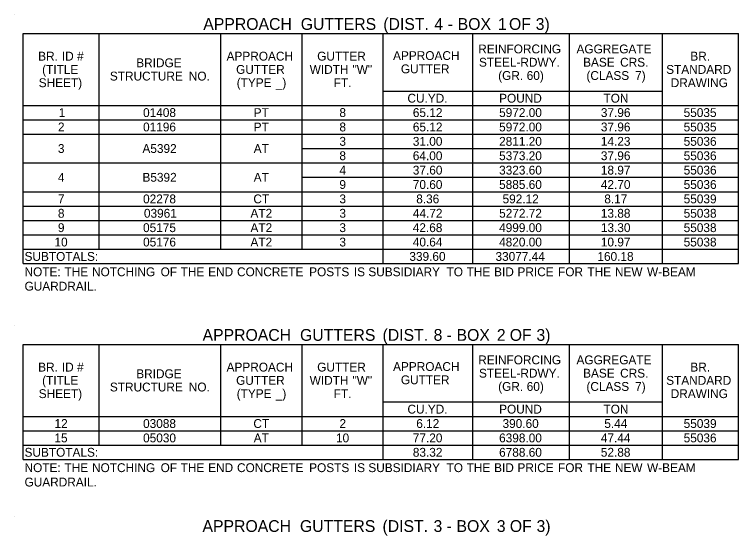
# Model space of a CAD drawing. Extents: x 540541 to 1930787, y -1948574 to 596640.
# Drawn here: x 544342.1 to 544833.1, y -1948134.4 to -1947781.3 of the extents above; entities that cross this region are included whole.
import ezdxf

# ---------------------------------------------------------------- set-up
doc = ezdxf.new("R2010")
doc.units = 0
doc.layers.add('Default', color=7, linetype='Continuous')
doc.layers.add('R_Border', color=7, linetype='Continuous')

msp = doc.modelspace()

# ---------------------------------------------------------------- linework, layer by layer
at = {"layer": 'Default'}
for p, q in [((544347.93, -1947794.12), (544833.09, -1947794.12)), ((544347.93, -1947950.12), (544347.93, -1947794.12)), ((544347.93, -1947950.12), (544347.93, -1947794.12)), ((544399.41, -1947940.37), (544399.41, -1947794.12)), ((544482.09, -1947940.37), (544482.09, -1947794.12)), ((544537.08, -1947940.37), (544537.08, -1947794.12)), ((544592.07, -1947950.12), (544592.07, -1947794.12)), ((544652.91, -1947940.37), (544652.91, -1947794.12)), ((544718.43, -1947940.37), (544718.43, -1947794.12)), ((544781.61, -1947842.87), (544781.61, -1947794.12)), ((544781.61, -1947950.12), (544781.61, -1947794.12)), ((544833.09, -1947950.12), (544833.09, -1947794.12)), ((544592.07, -1947833.12), (544781.61, -1947833.12)), ((544652.91, -1947881.87), (544652.91, -1947833.12)), ((544718.43, -1947881.87), (544718.43, -1947833.12)), ((544347.93, -1947842.87), (544781.61, -1947842.87)), ((544399.41, -1947862.37), (544399.41, -1947842.87)), ((544482.09, -1947852.62), (544482.09, -1947842.87)), ((544781.61, -1947842.87), (544833.09, -1947842.87)), ((544347.93, -1947852.62), (544781.61, -1947852.62)), ((544592.07, -1947852.62), (544718.43, -1947852.62)), ((544718.43, -1947852.62), (544833.09, -1947852.62)), ((544347.93, -1947862.37), (544781.61, -1947862.37)), ((544592.07, -1947862.37), (544718.43, -1947862.37)), ((544718.43, -1947862.37), (544833.09, -1947862.37)), ((544781.61, -1947881.87), (544781.61, -1947862.37)), ((544537.08, -1947872.12), (544781.61, -1947872.12)), ((544592.07, -1947872.12), (544718.43, -1947872.12)), ((544718.43, -1947872.12), (544833.09, -1947872.12)), ((544347.93, -1947881.87), (544833.09, -1947881.87)), ((544592.07, -1947881.87), (544718.43, -1947881.87)), ((544718.43, -1947881.87), (544833.09, -1947881.87)), ((544537.08, -1947891.62), (544718.43, -1947891.62)), ((544537.08, -1947891.62), (544652.91, -1947891.62)), ((544652.91, -1947891.62), (544833.09, -1947891.62)), ((544718.43, -1947901.37), (544718.43, -1947891.62)), ((544781.61, -1947901.37), (544781.61, -1947891.62)), ((544347.93, -1947901.37), (544537.08, -1947901.37)), ((544347.93, -1947901.37), (544482.09, -1947901.37)), ((544399.41, -1947940.37), (544399.41, -1947901.37)), ((544482.09, -1947901.37), (544833.09, -1947901.37)), ((544482.09, -1947911.12), (544482.09, -1947901.37)), ((544718.43, -1947901.37), (544833.09, -1947901.37)), ((544347.93, -1947911.12), (544833.09, -1947911.12)), ((544347.93, -1947920.87), (544833.09, -1947920.87)), ((544482.09, -1947940.37), (544482.09, -1947920.87)), ((544347.93, -1947930.62), (544833.09, -1947930.62)), ((544347.93, -1947940.37), (544833.09, -1947940.37)), ((544592.07, -1947950.12), (544592.07, -1947940.37)), ((544652.91, -1947950.12), (544652.91, -1947940.37)), ((544652.91, -1947950.12), (544652.91, -1947940.37)), ((544718.43, -1947950.12), (544718.43, -1947940.37)), ((544718.43, -1947950.12), (544718.43, -1947940.37)), ((544781.61, -1947950.12), (544781.61, -1947940.37)), ((544347.93, -1947950.12), (544833.09, -1947950.12)), ((544347.93, -1948004.88), (544833.09, -1948004.88)), ((544347.93, -1948082.88), (544347.93, -1948004.88)), ((544347.93, -1948082.88), (544347.93, -1948004.88)), ((544399.41, -1948073.13), (544399.41, -1948004.88)), ((544482.09, -1948073.13), (544482.09, -1948004.88)), ((544537.08, -1948073.13), (544537.08, -1948004.88)), ((544592.07, -1948082.88), (544592.07, -1948004.88)), ((544652.91, -1948082.88), (544652.91, -1948004.88)), ((544718.43, -1948082.88), (544718.43, -1948004.88)), ((544781.61, -1948053.63), (544781.61, -1948004.88)), ((544781.61, -1948082.88), (544781.61, -1948004.88)), ((544833.09, -1948082.88), (544833.09, -1948004.88)), ((544592.07, -1948043.88), (544781.61, -1948043.88)), ((544652.91, -1948053.63), (544652.91, -1948043.88)), ((544718.43, -1948053.63), (544718.43, -1948043.88)), ((544347.93, -1948053.63), (544833.09, -1948053.63)), ((544399.41, -1948063.38), (544399.41, -1948053.63)), ((544482.09, -1948063.38), (544482.09, -1948053.63)), ((544781.61, -1948053.63), (544833.09, -1948053.63)), ((544347.93, -1948063.38), (544718.43, -1948063.38)), ((544347.93, -1948063.38), (544652.91, -1948063.38)), ((544652.91, -1948063.38), (544833.09, -1948063.38)), ((544347.93, -1948073.13), (544833.09, -1948073.13)), ((544592.07, -1948082.88), (544592.07, -1948073.13)), ((544652.91, -1948082.88), (544652.91, -1948073.13)), ((544718.43, -1948082.88), (544718.43, -1948073.13)), ((544781.61, -1948082.88), (544781.61, -1948073.13)), ((544347.93, -1948082.88), (544833.09, -1948082.88))]:
    msp.add_line(p, q, dxfattribs=at)
at = {"layer": 'R_Border'}
for p, q in [((544342.08, -1947781.25), (544342.08, -1947781.25)), ((544342.08, -1947992.01), (544342.08, -1947992.01)), ((544342.08, -1948121.57), (544342.08, -1948121.57))]:
    msp.add_line(p, q, dxfattribs=at)

# ---------------------------------------------------------------- texts
at = {"layer": 'Default'}
for s, height, p in [('APPROACH', 8, (544470.13, -1947791.69)), (' GUTTERS', 8, (544533.25, -1947791.69)), (' (DIST.', 8, (544589.22, -1947791.69)), (' 4', 8, (544623.84, -1947791.69)), (' BOX', 8, (544639.65, -1947791.69)), (' 1', 8, (544666.96, -1947791.69)), (' OF', 8, (544674.47, -1947791.69)), (' 3)', 8, (544692.58, -1947791.69)), (' -', 8, (544632.9, -1947791.69)), ('REINFORCING', 6, (544656.58, -1947807.62)), ('AGGREGATE', 6, (544723.21, -1947807.62)), ('BR.', 6, (544358.15, -1947812.5)), (' ID', 6, (544372.01, -1947812.5)), (' #', 6, (544382.3, -1947812.5)), ('APPROACH', 6, (544485.92, -1947812.5)), ('GUTTER', 6, (544547.36, -1947812.5)), ('APPROACH', 6, (544598.82, -1947812.12)), ('BR.', 6, (544800.42, -1947812.5)), ('BRIDGE', 6, (544424.66, -1947817)), ('STEEL-RDWY.', 6, (544657.08, -1947816.62)), ('BASE', 6, (544727.69, -1947816.62)), (' CRS.', 6, (544750.57, -1947816.62)), ('(TITLE', 6, (544360.84, -1947821.5)), ('GUTTER', 6, (544492.37, -1947821.5)), ('WIDTH', 6, (544542.28, -1947821.5)), (' "W"', 6, (544569.1, -1947821.5)), ('GUTTER', 6, (544604.11, -1947821.12)), ('STANDARD', 6, (544784.04, -1947821.5)), ('STRUCTURE', 6, (544406.78, -1947826)), (' NO.', 6, (544458.07, -1947826)), ('(GR.', 6, (544670.11, -1947825.62)), (' 60)', 6, (544687.23, -1947825.62)), ('(CLASS', 6, (544729.95, -1947825.62)), (' 7)', 6, (544760.75, -1947825.62)), ('SHEET)', 6, (544358.51, -1947830.5)), ('(TYPE', 6, (544492.78, -1947830.5)), (' _)', 6, (544517.05, -1947830.5)), ('FT.', 6, (544558.58, -1947830.5)), ('DRAWING', 6, (544787.11, -1947830.5)), ('CU.YD.', 6, (544608.57, -1947841)), ('POUND', 6, (544670.74, -1947841)), ('TON', 6, (544741.51, -1947841)), ('1', 6, (544372.11, -1947850.75)), ('01408', 6, (544429.29, -1947850.75)), ('PT', 6, (544504.31, -1947850.75)), ('8', 6, (544562.43, -1947850.75)), ('65.12', 6, (544612.23, -1947850.75)), ('5972.00', 6, (544670.73, -1947850.75)), ('37.96', 6, (544739.73, -1947850.75)), ('55035', 6, (544795.87, -1947850.75)), ('2', 6, (544371.56, -1947860.5)), ('01196', 6, (544429.29, -1947860.5)), ('PT', 6, (544504.31, -1947860.5)), ('8', 6, (544562.43, -1947860.5)), ('65.12', 6, (544612.23, -1947860.5)), ('5972.00', 6, (544670.73, -1947860.5)), ('37.96', 6, (544739.73, -1947860.5)), ('55035', 6, (544795.87, -1947860.5)), ('3', 6, (544562.44, -1947870.25)), ('31.00', 6, (544612.21, -1947870.25)), ('2811.20', 6, (544670.73, -1947870.25)), ('14.23', 6, (544739.73, -1947870.25)), ('55036', 6, (544795.89, -1947870.25)), ('3', 6, (544371.53, -1947875.12)), ('A5392', 6, (544428.86, -1947875.12)), ('AT', 6, (544504.31, -1947875.12)), ('8', 6, (544562.43, -1947880)), ('64.00', 6, (544612.21, -1947880)), ('5373.20', 6, (544670.73, -1947880)), ('37.96', 6, (544739.73, -1947880)), ('55036', 6, (544795.89, -1947880)), ('4', 6, (544562.45, -1947889.75)), ('37.60', 6, (544612.21, -1947889.75)), ('3323.60', 6, (544670.73, -1947889.75)), ('18.97', 6, (544739.73, -1947889.75)), ('55036', 6, (544795.89, -1947889.75)), ('4', 6, (544371.54, -1947894.62)), ('B5392', 6, (544428.86, -1947894.62)), ('AT', 6, (544504.31, -1947894.62)), ('9', 6, (544562.43, -1947899.5)), ('70.60', 6, (544612.21, -1947899.5)), ('5885.60', 6, (544670.73, -1947899.5)), ('42.70', 6, (544739.74, -1947899.5)), ('55036', 6, (544795.89, -1947899.5)), ('7', 6, (544371.53, -1947909.25)), ('02278', 6, (544429.29, -1947909.25)), ('CT', 6, (544504.08, -1947909.25)), ('3', 6, (544562.44, -1947909.25)), ('8.36', 6, (544614.53, -1947909.25)), ('592.12', 6, (544673.08, -1947909.25)), ('8.17', 6, (544742.06, -1947909.25)), ('55039', 6, (544795.89, -1947909.25)), ('8', 6, (544371.53, -1947919)), ('03961', 6, (544429.87, -1947919)), ('AT2', 6, (544502.12, -1947919)), ('3', 6, (544562.44, -1947919)), ('44.72', 6, (544612.23, -1947919)), ('5272.72', 6, (544670.75, -1947919)), ('13.88', 6, (544739.72, -1947919)), ('55038', 6, (544795.89, -1947919)), ('9', 6, (544371.53, -1947928.75)), ('05175', 6, (544429.27, -1947928.75)), ('AT2', 6, (544502.12, -1947928.75)), ('3', 6, (544562.44, -1947928.75)), ('42.68', 6, (544612.19, -1947928.75)), ('4999.00', 6, (544670.73, -1947928.75)), ('13.30', 6, (544739.74, -1947928.75)), ('55038', 6, (544795.89, -1947928.75)), ('10', 6, (544369.21, -1947938.5)), ('05176', 6, (544429.29, -1947938.5)), ('AT2', 6, (544502.12, -1947938.5)), ('3', 6, (544562.44, -1947938.5)), ('40.64', 6, (544612.21, -1947938.5)), ('4820.00', 6, (544670.73, -1947938.5)), ('10.97', 6, (544739.73, -1947938.5)), ('55038', 6, (544795.89, -1947938.5)), ('SUBTOTALS:', 6, (544348.91, -1947948.25)), ('339.60', 6, (544609.88, -1947948.25)), ('33077.44', 6, (544668.29, -1947948.25)), ('160.18', 6, (544737.39, -1947948.25)), ('NOTE:', 6, (544348.91, -1947958.67)), (' THE', 6, (544373.79, -1947958.67)), (' NOTCHING', 6, (544392.44, -1947958.67)), (' OF', 6, (544438.96, -1947958.67)), (' THE', 6, (544452.54, -1947958.67)), (' END', 6, (544471.19, -1947958.67)), (' CONCRETE', 6, (544490.77, -1947958.67)), (' POSTS', 6, (544539.7, -1947958.67)), (' IS', 6, (544570.01, -1947958.67)), (' SUBSIDIARY', 6, (544579.82, -1947958.67)), (' TO', 6, (544632.87, -1947958.67)), (' THE', 6, (544646.47, -1947958.67)), (' BID', 6, (544665.12, -1947958.67)), (' PRICE', 6, (544680.97, -1947958.67)), (' FOR', 6, (544708.48, -1947958.67)), (' THE', 6, (544728.39, -1947958.67)), (' NEW', 6, (544747.04, -1947958.67)), (' W-BEAM', 6, (544768.83, -1947958.67)), ('GUARDRAIL.', 6, (544348.91, -1947968.42)), ('APPROACH', 8, (544469.63, -1948002.45)), (' GUTTERS', 8, (544532.75, -1948002.45)), (' (DIST.', 8, (544588.72, -1948002.45)), (' 8', 8, (544623.34, -1948002.45)), (' BOX', 8, (544638.9, -1948002.45)), (' 2', 8, (544666.22, -1948002.45)), (' OF', 8, (544674.97, -1948002.45)), (' 3)', 8, (544693.08, -1948002.45)), (' -', 8, (544632.16, -1948002.45)), ('REINFORCING', 6, (544656.58, -1948018.38)), ('AGGREGATE', 6, (544723.21, -1948018.38)), ('BR.', 6, (544358.15, -1948023.26)), (' ID', 6, (544372.01, -1948023.26)), (' #', 6, (544382.3, -1948023.26)), ('APPROACH', 6, (544485.92, -1948023.26)), ('GUTTER', 6, (544547.36, -1948023.26)), ('APPROACH', 6, (544598.82, -1948022.88)), ('BR.', 6, (544800.42, -1948023.26)), ('BRIDGE', 6, (544424.66, -1948027.76)), ('STEEL-RDWY.', 6, (544657.08, -1948027.38)), ('BASE', 6, (544727.69, -1948027.38)), (' CRS.', 6, (544750.57, -1948027.38)), ('(TITLE', 6, (544360.84, -1948032.26)), ('GUTTER', 6, (544492.37, -1948032.26)), ('WIDTH', 6, (544542.28, -1948032.26)), (' "W"', 6, (544569.1, -1948032.26)), ('GUTTER', 6, (544604.11, -1948031.88)), ('STANDARD', 6, (544784.04, -1948032.26)), ('STRUCTURE', 6, (544406.78, -1948036.76)), (' NO.', 6, (544458.07, -1948036.76)), ('(GR.', 6, (544670.11, -1948036.38)), (' 60)', 6, (544687.23, -1948036.38)), ('(CLASS', 6, (544729.95, -1948036.38)), (' 7)', 6, (544760.75, -1948036.38)), ('SHEET)', 6, (544358.51, -1948041.26)), ('(TYPE', 6, (544492.78, -1948041.26)), (' _)', 6, (544517.05, -1948041.26)), ('FT.', 6, (544558.58, -1948041.26)), ('DRAWING', 6, (544787.11, -1948041.26)), ('CU.YD.', 6, (544608.57, -1948051.76)), ('POUND', 6, (544670.74, -1948051.76)), ('TON', 6, (544741.51, -1948051.76)), ('12', 6, (544369.23, -1948061.51)), ('03088', 6, (544429.29, -1948061.51)), ('CT', 6, (544504.08, -1948061.51)), ('2', 6, (544562.47, -1948061.51)), ('6.12', 6, (544614.56, -1948061.51)), ('390.60', 6, (544673.06, -1948061.51)), ('5.44', 6, (544742.07, -1948061.51)), ('55039', 6, (544795.89, -1948061.51)), ('15', 6, (544369.18, -1948071.26)), ('05030', 6, (544429.3, -1948071.26)), ('AT', 6, (544504.31, -1948071.26)), ('10', 6, (544560.12, -1948071.26)), ('77.20', 6, (544612.21, -1948071.26)), ('6398.00', 6, (544670.73, -1948071.26)), ('47.44', 6, (544739.74, -1948071.26)), ('55036', 6, (544795.89, -1948071.26)), ('SUBTOTALS:', 6, (544348.91, -1948081.01)), ('83.32', 6, (544612.22, -1948081.01)), ('6788.60', 6, (544670.73, -1948081.01)), ('52.88', 6, (544739.72, -1948081.01)), ('NOTE:', 6, (544348.91, -1948091.43)), (' THE', 6, (544373.79, -1948091.43)), (' NOTCHING', 6, (544392.44, -1948091.43)), (' OF', 6, (544438.96, -1948091.43)), (' THE', 6, (544452.54, -1948091.43)), (' END', 6, (544471.19, -1948091.43)), (' CONCRETE', 6, (544490.77, -1948091.43)), (' POSTS', 6, (544539.7, -1948091.43)), (' IS', 6, (544570.01, -1948091.43)), (' SUBSIDIARY', 6, (544579.82, -1948091.43)), (' TO', 6, (544632.87, -1948091.43)), (' THE', 6, (544646.47, -1948091.43)), (' BID', 6, (544665.12, -1948091.43)), (' PRICE', 6, (544680.97, -1948091.43)), (' FOR', 6, (544708.48, -1948091.43)), (' THE', 6, (544728.39, -1948091.43)), (' NEW', 6, (544747.04, -1948091.43)), (' W-BEAM', 6, (544768.83, -1948091.43)), ('GUARDRAIL.', 6, (544348.91, -1948101.18)), ('APPROACH', 8, (544469.58, -1948132)), (' GUTTERS', 8, (544532.7, -1948132)), (' (DIST.', 8, (544588.67, -1948132)), (' 3', 8, (544623.29, -1948132)), (' BOX', 8, (544638.87, -1948132)), (' 3', 8, (544666.19, -1948132)), (' OF', 8, (544675.02, -1948132)), (' 3)', 8, (544693.13, -1948132)), (' -', 8, (544632.13, -1948132))]:
    msp.add_text(s, height=height, dxfattribs=at).set_placement(p)

doc.saveas('drawing.dxf')
